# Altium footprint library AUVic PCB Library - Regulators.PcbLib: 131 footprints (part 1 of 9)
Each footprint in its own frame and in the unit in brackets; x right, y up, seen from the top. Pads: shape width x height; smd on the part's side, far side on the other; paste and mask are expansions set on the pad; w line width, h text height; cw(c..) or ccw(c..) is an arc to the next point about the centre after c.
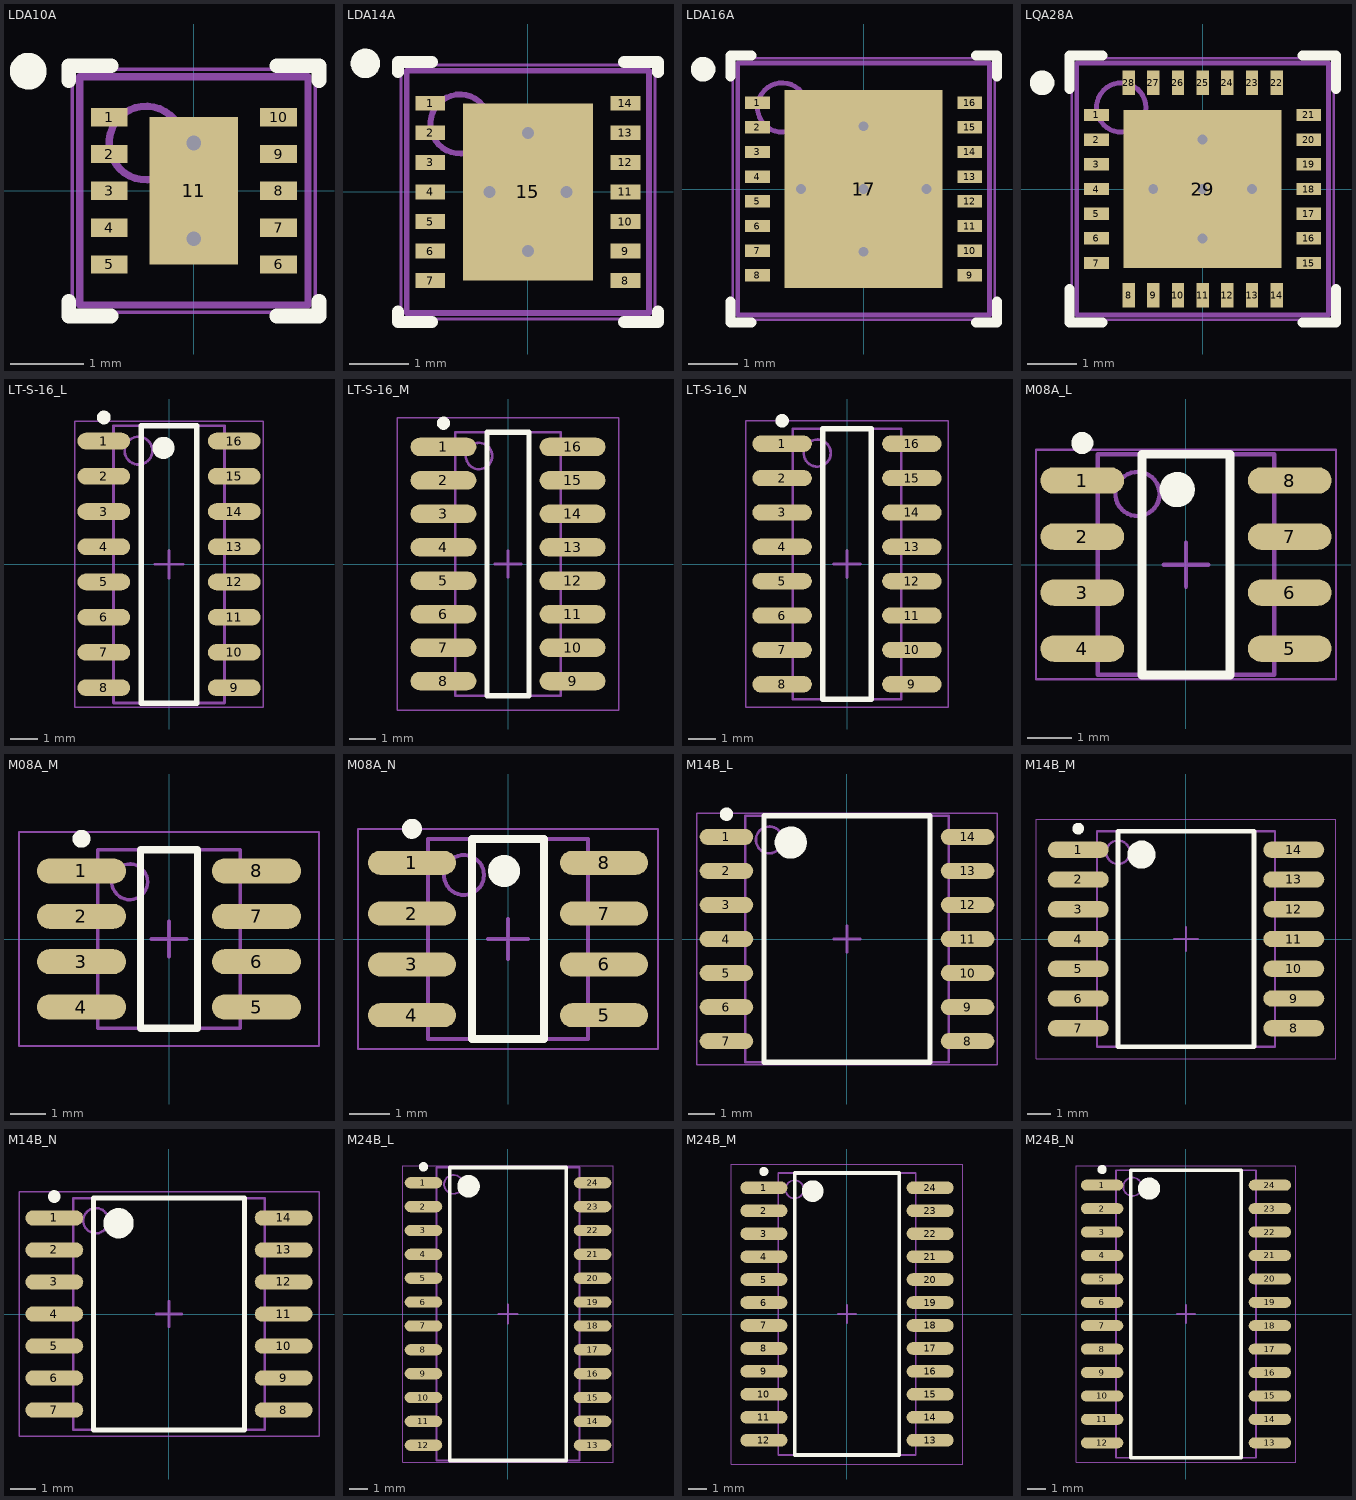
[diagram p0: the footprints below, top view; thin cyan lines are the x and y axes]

## LDA10A [mm] "PSON, 10-Leads, Body 3x3mm, Pitch 0.5mm, NSC Recommended"
height 0.8
pads (11):
  rect 0.5x0.25 smd paste-0.125 mask+0.051: 1(-1.15,1) 2(-1.15,0.5) 3(-1.15,0) 4(-1.15,-0.5) 5(-1.15,-1) 6(1.15,-1) 7(1.15,-0.5) 8(1.15,0) 9(1.15,0.5) 10(1.15,1)
  rect 1.2x2 smd paste-0.6 mask+0.051: 11(0,0)
via 0,-0.65 diameter 0.5 hole 0.2
via 0,0.65 diameter 0.5 hole 0.2
Top Overlay:
  circle w0.25: c-2.25,1.625 r0.125
  lines w0.2: -1.7,-1.5 -1.7,-1.7 -1.125,-1.7 ; -1.7,1.5 -1.7,1.7 -1.125,1.7 ; 1.125,-1.7 1.7,-1.7 1.7,-1.5 ; 1.125,1.7 1.7,1.7 1.7,1.5
Top Paste:
  region: 1.5,-0.875 1,-0.875 1,-1.125 1.5,-1.125
  region: 1.5,-0.375 1,-0.375 1,-0.625 1.5,-0.625
  region: 1.5,0.125 1,0.125 1,-0.125 1.5,-0.125
  region: 1.5,0.625 1,0.625 1,0.375 1.5,0.375
  region: 1.5,1.125 1,1.125 1,0.875 1.5,0.875
  rectangle: -1.5,-1.125 -1,-0.875
  rectangle: -1.5,-0.625 -1,-0.375
  rectangle: -1.5,-0.125 -1,0.125
  rectangle: -1.5,0.375 -1,0.625
  rectangle: -1.5,0.875 -1,1.125
  rectangle: -0.57,-0.95 0.57,0.95
Mechanical 13:
  circle w0.1: c-0.65,0.65 r0.5
  lines w0.1: -1.55,-1.55 1.55,-1.55 1.55,1.55 -1.55,1.55 -1.55,-1.55
Mechanical 15:
  lines w0.05: -1.65,-1.65 1.65,-1.65 1.65,1.65 -1.65,1.65 -1.65,-1.65
  lines w0.1: -0.5,0 0.5,0 ; 0,-0.5 0,0.5
3D body: height 0.8, standoff 0, extent -1.55,-1.55 1.55,1.55

## LDA14A [mm] "PSON, 14-Leads, Body 4x4mm, Pitch 0.5mm, NSC Recommended"
height 0.8
pads (15):
  rect 0.5x0.25 smd paste-0.125 mask+0.051: 1(-1.65,1.5) 2(-1.65,1) 3(-1.65,0.5) 4(-1.65,0) 5(-1.65,-0.5) 6(-1.65,-1) 7(-1.65,-1.5) 8(1.65,-1.5) 9(1.65,-1) 10(1.65,-0.5) 11(1.65,0) 12(1.65,0.5) 13(1.65,1) 14(1.65,1.5)
  rect 2.2x3 smd paste-1.3 mask+0.051: 15(0,0)
via 0,1 diameter 0.5 hole 0.2
via 0,-1 diameter 0.5 hole 0.2
via -0.65,0 diameter 0.5 hole 0.2
via 0.65,0 diameter 0.5 hole 0.2
Top Overlay:
  circle w0.25: c-2.75,2.175 r0.125
  lines w0.2: -2.2,-2.025 -2.2,-2.2 -1.625,-2.2 ; -2.2,2.025 -2.2,2.2 -1.625,2.2 ; 1.625,-2.2 2.2,-2.2 2.2,-2.025 ; 1.625,2.2 2.2,2.2 2.2,2.025
Top Paste:
  rectangle: -1,0.1 -0.1,1.4
  rectangle: -1,-1.4 -0.1,-0.1
  region: 1,-0.1 0.1,-0.1 0.1,-1.4 1,-1.4
  region: 1,1.4 0.1,1.4 0.1,0.1 1,0.1
  rectangle: 1.5,1.375 2,1.625
  rectangle: 1.5,0.875 2,1.125
  rectangle: 1.5,0.375 2,0.625
  rectangle: 1.5,-0.125 2,0.125
  rectangle: 1.5,-0.625 2,-0.375
  rectangle: 1.5,-1.125 2,-0.875
  rectangle: 1.5,-1.625 2,-1.375
  region: -1.5,-1.375 -2,-1.375 -2,-1.625 -1.5,-1.625
  region: -1.5,-0.875 -2,-0.875 -2,-1.125 -1.5,-1.125
  region: -1.5,-0.375 -2,-0.375 -2,-0.625 -1.5,-0.625
  region: -1.5,0.125 -2,0.125 -2,-0.125 -1.5,-0.125
  region: -1.5,0.625 -2,0.625 -2,0.375 -1.5,0.375
  region: -1.5,1.125 -2,1.125 -2,0.875 -1.5,0.875
  region: -1.5,1.625 -2,1.625 -2,1.375 -1.5,1.375
Mechanical 13:
  circle w0.1: c-1.15,1.15 r0.5
  lines w0.1: -2.05,-2.05 2.05,-2.05 2.05,2.05 -2.05,2.05 -2.05,-2.05
Mechanical 15:
  lines w0.05: -2.15,-2.15 -2.15,2.15 2.15,2.15 2.15,-2.15 -2.15,-2.15
  lines w0.1: -0.5,0 0.5,0 ; 0,-0.5 0,0.5
3D body: height 0.8, standoff 0, extent -2.049,-2.049 2.049,2.049

## LDA16A [mm] "PSON, 16-Leads, Body 5x5 mm, Pitch 0.5mm, NSC Recommended"
height 0.8
pads (17):
  rect 0.5x0.25 smd paste-0.125 mask+0.051: 1(-2.15,1.75) 2(-2.15,1.25) 3(-2.15,0.75) 4(-2.15,0.25) 5(-2.15,-0.25) 6(-2.15,-0.75) 7(-2.15,-1.25) 8(-2.15,-1.75) 9(2.15,-1.75) 10(2.15,-1.25) 11(2.15,-0.75) 12(2.15,-0.25) 13(2.15,0.25) 14(2.15,0.75) 15(2.15,1.25) 16(2.15,1.75)
  rect 3.2x4 smd paste-1.6 mask+0.051: 17(0,0)
via -1.27,0 diameter 0.5 hole 0.2
via 0,-1.27 diameter 0.5 hole 0.2
via 0,0 diameter 0.5 hole 0.2
via 0,1.27 diameter 0.5 hole 0.2
via 1.27,0 diameter 0.5 hole 0.2
Top Overlay:
  circle w0.25: c-3.25,2.425 r0.125
  lines w0.2: -2.7,-2.275 -2.7,-2.7 -2.275,-2.7 ; -2.7,2.275 -2.7,2.7 -2.275,2.7 ; 2.275,-2.7 2.7,-2.7 2.7,-2.275 ; 2.275,2.7 2.7,2.7 2.7,2.275
Top Paste:
  rectangle: 0.1,0.1 1.5,2
  region: -0.1,2 -1.5,2 -1.5,0.1 -0.1,0.1
  region: -0.1,-0.1 -1.5,-0.1 -1.5,-2 -0.1,-2
  rectangle: 0.1,-2 1.5,-0.1
  rectangle: -2.5,1.625 -2,1.875
  rectangle: -2.5,1.125 -2,1.375
  rectangle: -2.5,0.625 -2,0.875
  rectangle: -2.5,0.125 -2,0.375
  rectangle: -2.5,-0.875 -2,-0.625
  rectangle: -2.5,-1.375 -2,-1.125
  rectangle: -2.5,-1.875 -2,-1.625
  rectangle: -2.5,-0.375 -2,-0.125
  region: 2.5,-0.125 2,-0.125 2,-0.375 2.5,-0.375
  region: 2.5,-1.625 2,-1.625 2,-1.875 2.5,-1.875
  region: 2.5,-1.125 2,-1.125 2,-1.375 2.5,-1.375
  region: 2.5,-0.625 2,-0.625 2,-0.875 2.5,-0.875
  region: 2.5,0.375 2,0.375 2,0.125 2.5,0.125
  region: 2.5,0.875 2,0.875 2,0.625 2.5,0.625
  region: 2.5,1.375 2,1.375 2,1.125 2.5,1.125
  region: 2.5,1.875 2,1.875 2,1.625 2.5,1.625
Mechanical 13:
  circle w0.1: c-1.65,1.65 r0.5
  lines w0.1: -2.55,-2.55 -2.55,2.55 2.55,2.55 2.55,-2.55 -2.55,-2.55
Mechanical 15:
  lines w0.05: -2.65,-2.65 2.65,-2.65 2.65,2.65 -2.65,2.65 -2.65,-2.65
  lines w0.1: -0.5,0 0.5,0 ; 0,-0.5 0,0.5
3D body: height 0.8, standoff 0, extent -2.55,-2.55 2.55,2.55

## LQA28A [mm] "PQFN, 28-Leads, Body 5x5mm, Pitch 0.5mm, NSC Recommended"
height 0.8
pads (29):
  rect 0.5x0.25 smd paste-0.125 mask+0.051: 1(-2.15,1.5) 2(-2.15,1) 3(-2.15,0.5) 4(-2.15,0) 5(-2.15,-0.5) 6(-2.15,-1) 7(-2.15,-1.5) 15(2.15,-1.5) 16(2.15,-1) 17(2.15,-0.5) 18(2.15,0) 19(2.15,0.5) 20(2.15,1) 21(2.15,1.5)
  rect 0.25x0.5 smd paste-0.125 mask+0.051: 8(-1.5,-2.15) 9(-1,-2.15) 10(-0.5,-2.15) 11(0,-2.15) 12(0.5,-2.15) 13(1,-2.15) 14(1.5,-2.15) 22(1.5,2.15) 23(1,2.15) 24(0.5,2.15) 25(0,2.15) 26(-0.5,2.15) 27(-1,2.15) 28(-1.5,2.15)
  rect 3.2x3.2 smd paste-1.6 mask+0.051: 29(0,0)
via 0,-1 diameter 0.5 hole 0.2
via 1,0 diameter 0.5 hole 0.2
via 0,0 diameter 0.5 hole 0.2
via -1,0 diameter 0.5 hole 0.2
via 0,1 diameter 0.5 hole 0.2
Top Overlay:
  circle w0.25: c-3.25,2.15 r0.125
  lines w0.2: -2.7,-2.025 -2.7,-2.7 -2.025,-2.7 ; -2.7,2.025 -2.7,2.7 -2.025,2.7 ; 2.025,-2.7 2.7,-2.7 2.7,-2.025 ; 2.025,2.7 2.7,2.7 2.7,2.025
Top Paste:
  rectangle: 0.15,-1.5 1.5,-0.15
  region: -0.15,-0.15 -1.5,-0.15 -1.5,-1.5 -0.15,-1.5
  region: -0.15,1.5 -1.5,1.5 -1.5,0.15 -0.15,0.15
  rectangle: 0.15,0.15 1.5,1.5
  region: 1.625,-2.5 1.625,-2 1.375,-2 1.375,-2.5
  region: 1.125,-2.5 1.125,-2 0.875,-2 0.875,-2.5
  region: 0.625,-2.5 0.625,-2 0.375,-2 0.375,-2.5
  region: 0.125,-2.5 0.125,-2 -0.125,-2 -0.125,-2.5
  region: -0.375,-2.5 -0.375,-2 -0.625,-2 -0.625,-2.5
  region: -0.875,-2.5 -0.875,-2 -1.125,-2 -1.125,-2.5
  region: -1.375,-2.5 -1.375,-2 -1.625,-2 -1.625,-2.5
  region: -1.625,2.5 -1.625,2 -1.375,2 -1.375,2.5
  region: -1.125,2.5 -1.125,2 -0.875,2 -0.875,2.5
  region: -0.625,2.5 -0.625,2 -0.375,2 -0.375,2.5
  region: -0.125,2.5 -0.125,2 0.125,2 0.125,2.5
  region: 0.375,2.5 0.375,2 0.625,2 0.625,2.5
  region: 0.875,2.5 0.875,2 1.125,2 1.125,2.5
  region: 1.375,2.5 1.375,2 1.625,2 1.625,2.5
  region: 2.5,1.625 2,1.625 2,1.375 2.5,1.375
  region: 2.5,1.125 2,1.125 2,0.875 2.5,0.875
  region: 2.5,0.625 2,0.625 2,0.375 2.5,0.375
  region: 2.5,0.125 2,0.125 2,-0.125 2.5,-0.125
  region: 2.5,-0.375 2,-0.375 2,-0.625 2.5,-0.625
  region: 2.5,-0.875 2,-0.875 2,-1.125 2.5,-1.125
  region: 2.5,-1.375 2,-1.375 2,-1.625 2.5,-1.625
  rectangle: -2.5,-1.625 -2,-1.375
  rectangle: -2.5,-1.125 -2,-0.875
  rectangle: -2.5,-0.625 -2,-0.375
  rectangle: -2.5,-0.125 -2,0.125
  rectangle: -2.5,0.375 -2,0.625
  rectangle: -2.5,0.875 -2,1.125
  rectangle: -2.5,1.375 -2,1.625
Mechanical 13:
  circle w0.1: c-1.65,1.65 r0.5
  lines w0.1: -2.55,-2.55 2.55,-2.55 2.55,2.55 -2.55,2.55 -2.55,-2.55
Mechanical 15:
  lines w0.05: -2.65,-2.65 2.65,-2.65 2.65,2.65 -2.65,2.65 -2.65,-2.65
  lines w0.1: -0.5,0 0.5,0 ; 0,-0.5 0,0.5
3D body: height 0.8, standoff 0, extent -2.55,-2.55 2.55,2.55

## LT-S-16_L [mm] "SOP, 16-Leads, Body 10x4mm, Pitch 1.27mm, IPC High Density"
height 1.76
pads (16):
  oval 1.9x0.6 smd: 1(-2.35,4.445) 2(-2.35,3.175) 3(-2.35,1.905) 4(-2.35,0.635) 5(-2.35,-0.635) 6(-2.35,-1.905) 7(-2.35,-3.175) 8(-2.35,-4.445) 9(2.35,-4.445) 10(2.35,-3.175) 11(2.35,-1.905) 12(2.35,-0.635) 13(2.35,0.635) 14(2.35,1.905) 15(2.35,3.175) 16(2.35,4.445)
Top Overlay:
  circle w0.25: c-2.35,5.295 r0.125
  circle w0.4: c-0.2,4.2 r0.2
  lines w0.2: -1,-5 -1,5 1,5 1,-5 -1,-5
Mechanical 13:
  circle w0.1: c-1.1,4.1 r0.5
  lines w0.1: -2,-5 -2,5 2,5 2,-5 -2,-5
Mechanical 15:
  lines w0.05: -3.4,-5.15 -3.4,5.15 3.4,5.15 3.4,-5.15 -3.4,-5.15
  lines w0.1: -0.5,0 0.5,0 ; 0,-0.5 0,0.5
3D body: height 1.76, standoff 0.1, extent -2,-5 2,5

## LT-S-16_M [mm] "SOP, 16-Leads, Body 10x4mm, Pitch 1.27mm, IPC Low Density"
height 1.76
pads (16):
  oval 2.5x0.7 smd: 1(-2.45,4.445) 2(-2.45,3.175) 3(-2.45,1.905) 4(-2.45,0.635) 5(-2.45,-0.635) 6(-2.45,-1.905) 7(-2.45,-3.175) 8(-2.45,-4.445) 9(2.45,-4.445) 10(2.45,-3.175) 11(2.45,-1.905) 12(2.45,-0.635) 13(2.45,0.635) 14(2.45,1.905) 15(2.45,3.175) 16(2.45,4.445)
Top Overlay:
  circle w0.25: c-2.45,5.345 r0.125
  lines w0.2: -0.8,-5 -0.8,5 0.8,5 0.8,-5 -0.8,-5
Mechanical 13:
  circle w0.1: c-1.1,4.1 r0.5
  lines w0.1: -2,-5 -2,5 2,5 2,-5 -2,-5
Mechanical 15:
  lines w0.05: -4.2,-5.55 -4.2,5.55 4.2,5.55 4.2,-5.55 -4.2,-5.55
  lines w0.1: -0.5,0 0.5,0 ; 0,-0.5 0,0.5
3D body: height 1.76, standoff 0.1, extent -2,-5 2,5

## LT-S-16_N [mm] "SOP, 16-Leads, Body 10x4mm, Pitch 1.27mm, IPC Medium Density"
height 1.76
pads (16):
  oval 2.2x0.6 smd: 1(-2.4,4.445) 2(-2.4,3.175) 3(-2.4,1.905) 4(-2.4,0.635) 5(-2.4,-0.635) 6(-2.4,-1.905) 7(-2.4,-3.175) 8(-2.4,-4.445) 9(2.4,-4.445) 10(2.4,-3.175) 11(2.4,-1.905) 12(2.4,-0.635) 13(2.4,0.635) 14(2.4,1.905) 15(2.4,3.175) 16(2.4,4.445)
Top Overlay:
  circle w0.25: c-2.4,5.295 r0.125
  lines w0.2: -0.9,-5 0.9,-5 0.9,5 -0.9,5 -0.9,-5
Mechanical 13:
  circle w0.1: c-1.1,4.1 r0.5
  lines w0.1: -2,-5 2,-5 2,5 -2,5 -2,-5
Mechanical 15:
  lines w0.05: -3.75,-5.3 3.75,-5.3 3.75,5.3 -3.75,5.3 -3.75,-5.3
  lines w0.1: -0.5,0 0.5,0 ; 0,-0.5 0,0.5
3D body: height 1.76, standoff 0.1, extent -2,-5 2,5

## M08A_L [mm] "SOIC, 8-Leads, Body 4.9x3.9mm, Pitch 1.27mm, IPC High Density"
height 1.75
pads (8):
  oval 1.9x0.6 smd: 1(-2.35,1.905) 2(-2.35,0.635) 3(-2.35,-0.635) 4(-2.35,-1.905) 5(2.35,-1.905) 6(2.35,-0.635) 7(2.35,0.635) 8(2.35,1.905)
Top Overlay:
  circle w0.25: c-2.35,2.755 r0.125
  circle w0.4: c-0.2,1.7 r0.2
  lines w0.2: -1,-2.5 -1,2.5 1,2.5 1,-2.5 -1,-2.5
Mechanical 13:
  circle w0.1: c-1.1,1.6 r0.5
  lines w0.1: -2,-2.5 -2,2.5 2,2.5 2,-2.5 -2,-2.5
Mechanical 15:
  lines w0.05: -3.4,-2.6 -3.4,2.6 3.4,2.6 3.4,-2.6 -3.4,-2.6
  lines w0.1: -0.5,0 0.5,0 ; 0,-0.5 0,0.5
3D body: height 1.75, standoff 0.1, extent -2,-2.5 2,2.5

## M08A_M [mm] "SOIC, 8-Leads, Body 4.9x3.9mm, Pitch 1.27mm, IPC Low Density"
height 1.75
pads (8):
  oval 2.5x0.7 smd: 1(-2.45,1.905) 2(-2.45,0.635) 3(-2.45,-0.635) 4(-2.45,-1.905) 5(2.45,-1.905) 6(2.45,-0.635) 7(2.45,0.635) 8(2.45,1.905)
Top Overlay:
  circle w0.25: c-2.45,2.805 r0.125
  lines w0.2: -0.8,-2.5 0.8,-2.5 0.8,2.5 -0.8,2.5 -0.8,-2.5
Mechanical 13:
  circle w0.1: c-1.1,1.6 r0.5
  lines w0.1: -2,-2.5 2,-2.5 2,2.5 -2,2.5 -2,-2.5
Mechanical 15:
  lines w0.05: -4.2,-3 4.2,-3 4.2,3 -4.2,3 -4.2,-3
  lines w0.1: -0.5,0 0.5,0 ; 0,-0.5 0,0.5
3D body: height 1.75, standoff 0.1, extent -2,-2.5 2,2.5

## M08A_N [mm] "SOIC, 8-Leads, Body 4.9x3.9mm, Pitch 1.27mm, IPC Medium Density"
height 1.75
pads (8):
  oval 2.2x0.6 smd: 1(-2.4,1.905) 2(-2.4,0.635) 3(-2.4,-0.635) 4(-2.4,-1.905) 5(2.4,-1.905) 6(2.4,-0.635) 7(2.4,0.635) 8(2.4,1.905)
Top Overlay:
  circle w0.25: c-2.4,2.755 r0.125
  circle w0.4: c-0.1,1.7 r0.2
  lines w0.2: -0.9,-2.5 -0.9,2.5 0.9,2.5 0.9,-2.5 -0.9,-2.5
Mechanical 13:
  circle w0.1: c-1.1,1.6 r0.5
  lines w0.1: -2,-2.5 -2,2.5 2,2.5 2,-2.5 -2,-2.5
Mechanical 15:
  lines w0.05: -3.75,-2.75 -3.75,2.75 3.75,2.75 3.75,-2.75 -3.75,-2.75
  lines w0.1: -0.5,0 0.5,0 ; 0,-0.5 0,0.5
3D body: height 1.75, standoff 0.1, extent -2,-2.5 2,2.5

## M14B_L [mm] "SOIC, 14-Leads, Body 9x7.5mm, Pitch 1.27mm, IPC High Density"
height 2.65
pads (14):
  oval 2x0.6 smd: 1(-4.5,3.81) 2(-4.5,2.54) 3(-4.5,1.27) 4(-4.5,0) 5(-4.5,-1.27) 6(-4.5,-2.54) 7(-4.5,-3.81) 8(4.5,-3.81) 9(4.5,-2.54) 10(4.5,-1.27) 11(4.5,0) 12(4.5,1.27) 13(4.5,2.54) 14(4.5,3.81)
Top Overlay:
  circle w0.6: c-2.1,3.6 r0.3
  circle w0.25: c-4.5,4.66 r0.125
  lines w0.2: -3.1,-4.6 3.1,-4.6 3.1,4.6 -3.1,4.6 -3.1,-4.6
Mechanical 13:
  circle w0.1: c-2.9,3.7 r0.5
  lines w0.1: -3.8,-4.6 3.8,-4.6 3.8,4.6 -3.8,4.6 -3.8,-4.6
Mechanical 15:
  lines w0.05: -5.6,-4.7 5.6,-4.7 5.6,4.7 -5.6,4.7 -5.6,-4.7
  lines w0.1: -0.5,0 0.5,0 ; 0,-0.5 0,0.5
3D body: height 2.65, standoff 0.1, extent -3.8,-4.6 3.8,4.6

## M14B_M [mm] "SOIC, 14-Leads, Body 9x7.5mm, Pitch 1.27mm, IPC Low Density"
height 2.65
pads (14):
  oval 2.6x0.7 smd: 1(-4.6,3.81) 2(-4.6,2.54) 3(-4.6,1.27) 4(-4.6,0) 5(-4.6,-1.27) 6(-4.6,-2.54) 7(-4.6,-3.81) 8(4.6,-3.81) 9(4.6,-2.54) 10(4.6,-1.27) 11(4.6,0) 12(4.6,1.27) 13(4.6,2.54) 14(4.6,3.81)
Top Overlay:
  circle w0.25: c-4.6,4.71 r0.125
  circle w0.6: c-1.9,3.6 r0.3
  lines w0.2: -2.9,-4.6 -2.9,4.6 2.9,4.6 2.9,-4.6 -2.9,-4.6
Mechanical 13:
  circle w0.1: c-2.9,3.7 r0.5
  lines w0.1: -3.8,-4.6 -3.8,4.6 3.8,4.6 3.8,-4.6 -3.8,-4.6
Mechanical 15:
  lines w0.05: -6.4,-5.1 -6.4,5.1 6.4,5.1 6.4,-5.1 -6.4,-5.1
  lines w0.1: -0.5,0 0.5,0 ; 0,-0.5 0,0.5
3D body: height 2.65, standoff 0.1, extent -3.8,-4.6 3.8,4.6

## M14B_N [mm] "SOIC, 14-Leads, Body 9x7.5mm, Pitch 1.27mm, IPC Medium Density"
height 2.65
pads (14):
  oval 2.3x0.6 smd: 1(-4.55,3.81) 2(-4.55,2.54) 3(-4.55,1.27) 4(-4.55,0) 5(-4.55,-1.27) 6(-4.55,-2.54) 7(-4.55,-3.81) 8(4.55,-3.81) 9(4.55,-2.54) 10(4.55,-1.27) 11(4.55,0) 12(4.55,1.27) 13(4.55,2.54) 14(4.55,3.81)
Top Overlay:
  circle w0.25: c-4.55,4.66 r0.125
  circle w0.6: c-2,3.6 r0.3
  lines w0.2: -3,-4.6 -3,4.6 3,4.6 3,-4.6 -3,-4.6
Mechanical 13:
  circle w0.1: c-2.9,3.7 r0.5
  lines w0.1: -3.8,-4.6 -3.8,4.6 3.8,4.6 3.8,-4.6 -3.8,-4.6
Mechanical 15:
  lines w0.05: -5.95,-4.85 -5.95,4.85 5.95,4.85 5.95,-4.85 -5.95,-4.85
  lines w0.1: -0.5,0 0.5,0 ; 0,-0.5 0,0.5
3D body: height 2.65, standoff 0.1, extent -3.8,-4.6 3.8,4.6

## M24B_L [mm] "SOIC, 24-Leads, Body 15.4x7.5mm, Pitch 1.27mm, IPC High Density"
height 2.65
pads (24):
  oval 2x0.6 smd: 1(-4.5,6.985) 2(-4.5,5.715) 3(-4.5,4.445) 4(-4.5,3.175) 5(-4.5,1.905) 6(-4.5,0.635) 7(-4.5,-0.635) 8(-4.5,-1.905) 9(-4.5,-3.175) 10(-4.5,-4.445) 11(-4.5,-5.715) 12(-4.5,-6.985) 13(4.5,-6.985) 14(4.5,-5.715) 15(4.5,-4.445) 16(4.5,-3.175) 17(4.5,-1.905) 18(4.5,-0.635) 19(4.5,0.635) 20(4.5,1.905) 21(4.5,3.175) 22(4.5,4.445) 23(4.5,5.715) 24(4.5,6.985)
Top Overlay:
  circle w0.25: c-4.5,7.835 r0.125
  circle w0.6: c-2.1,6.8 r0.3
  lines w0.2: -3.1,-7.8 -3.1,7.8 3.1,7.8 3.1,-7.8 -3.1,-7.8
Mechanical 13:
  circle w0.1: c-2.9,6.9 r0.5
  lines w0.1: -3.8,-7.8 -3.8,7.8 3.8,7.8 3.8,-7.8 -3.8,-7.8
Mechanical 15:
  lines w0.05: -5.6,-7.9 -5.6,7.9 5.6,7.9 5.6,-7.9 -5.6,-7.9
  lines w0.1: -0.5,0 0.5,0 ; 0,-0.5 0,0.5
3D body: height 2.65, standoff 0.1, extent -3.8,-7.8 3.8,7.8

## M24B_M [mm] "SOIC, 24-Leads, Body 15.4x7.5mm, Pitch 1.27mm, IPC Low Density"
height 2.65
pads (24):
  oval 2.6x0.7 smd: 1(-4.6,6.985) 2(-4.6,5.715) 3(-4.6,4.445) 4(-4.6,3.175) 5(-4.6,1.905) 6(-4.6,0.635) 7(-4.6,-0.635) 8(-4.6,-1.905) 9(-4.6,-3.175) 10(-4.6,-4.445) 11(-4.6,-5.715) 12(-4.6,-6.985) 13(4.6,-6.985) 14(4.6,-5.715) 15(4.6,-4.445) 16(4.6,-3.175) 17(4.6,-1.905) 18(4.6,-0.635) 19(4.6,0.635) 20(4.6,1.905) 21(4.6,3.175) 22(4.6,4.445) 23(4.6,5.715) 24(4.6,6.985)
Top Overlay:
  circle w0.25: c-4.6,7.885 r0.125
  circle w0.6: c-1.9,6.8 r0.3
  lines w0.2: -2.9,-7.8 -2.9,7.8 2.9,7.8 2.9,-7.8 -2.9,-7.8
Mechanical 13:
  circle w0.1: c-2.9,6.9 r0.5
  lines w0.1: -3.8,-7.8 -3.8,7.8 3.8,7.8 3.8,-7.8 -3.8,-7.8
Mechanical 15:
  lines w0.05: -6.4,-8.3 -6.4,8.3 6.4,8.3 6.4,-8.3 -6.4,-8.3
  lines w0.1: -0.5,0 0.5,0 ; 0,-0.5 0,0.5
3D body: height 2.65, standoff 0.1, extent -3.8,-7.8 3.8,7.8

## M24B_N [mm] "SOIC, 24-Leads, Body 15.4x7.5mm, Pitch 1.27mm, IPC Medium Density"
height 2.65
pads (24):
  oval 2.3x0.6 smd: 1(-4.55,6.985) 2(-4.55,5.715) 3(-4.55,4.445) 4(-4.55,3.175) 5(-4.55,1.905) 6(-4.55,0.635) 7(-4.55,-0.635) 8(-4.55,-1.905) 9(-4.55,-3.175) 10(-4.55,-4.445) 11(-4.55,-5.715) 12(-4.55,-6.985) 13(4.55,-6.985) 14(4.55,-5.715) 15(4.55,-4.445) 16(4.55,-3.175) 17(4.55,-1.905) 18(4.55,-0.635) 19(4.55,0.635) 20(4.55,1.905) 21(4.55,3.175) 22(4.55,4.445) 23(4.55,5.715) 24(4.55,6.985)
Top Overlay:
  circle w0.25: c-4.55,7.835 r0.125
  circle w0.6: c-2,6.8 r0.3
  lines w0.2: -3,-7.8 -3,7.8 3,7.8 3,-7.8 -3,-7.8
Mechanical 13:
  circle w0.1: c-2.9,6.9 r0.5
  lines w0.1: -3.8,-7.8 -3.8,7.8 3.8,7.8 3.8,-7.8 -3.8,-7.8
Mechanical 15:
  lines w0.05: -5.95,-8.05 -5.95,8.05 5.95,8.05 5.95,-8.05 -5.95,-8.05
  lines w0.1: -0.5,0 0.5,0 ; 0,-0.5 0,0.5
3D body: height 2.65, standoff 0.1, extent -3.8,-7.8 3.8,7.8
